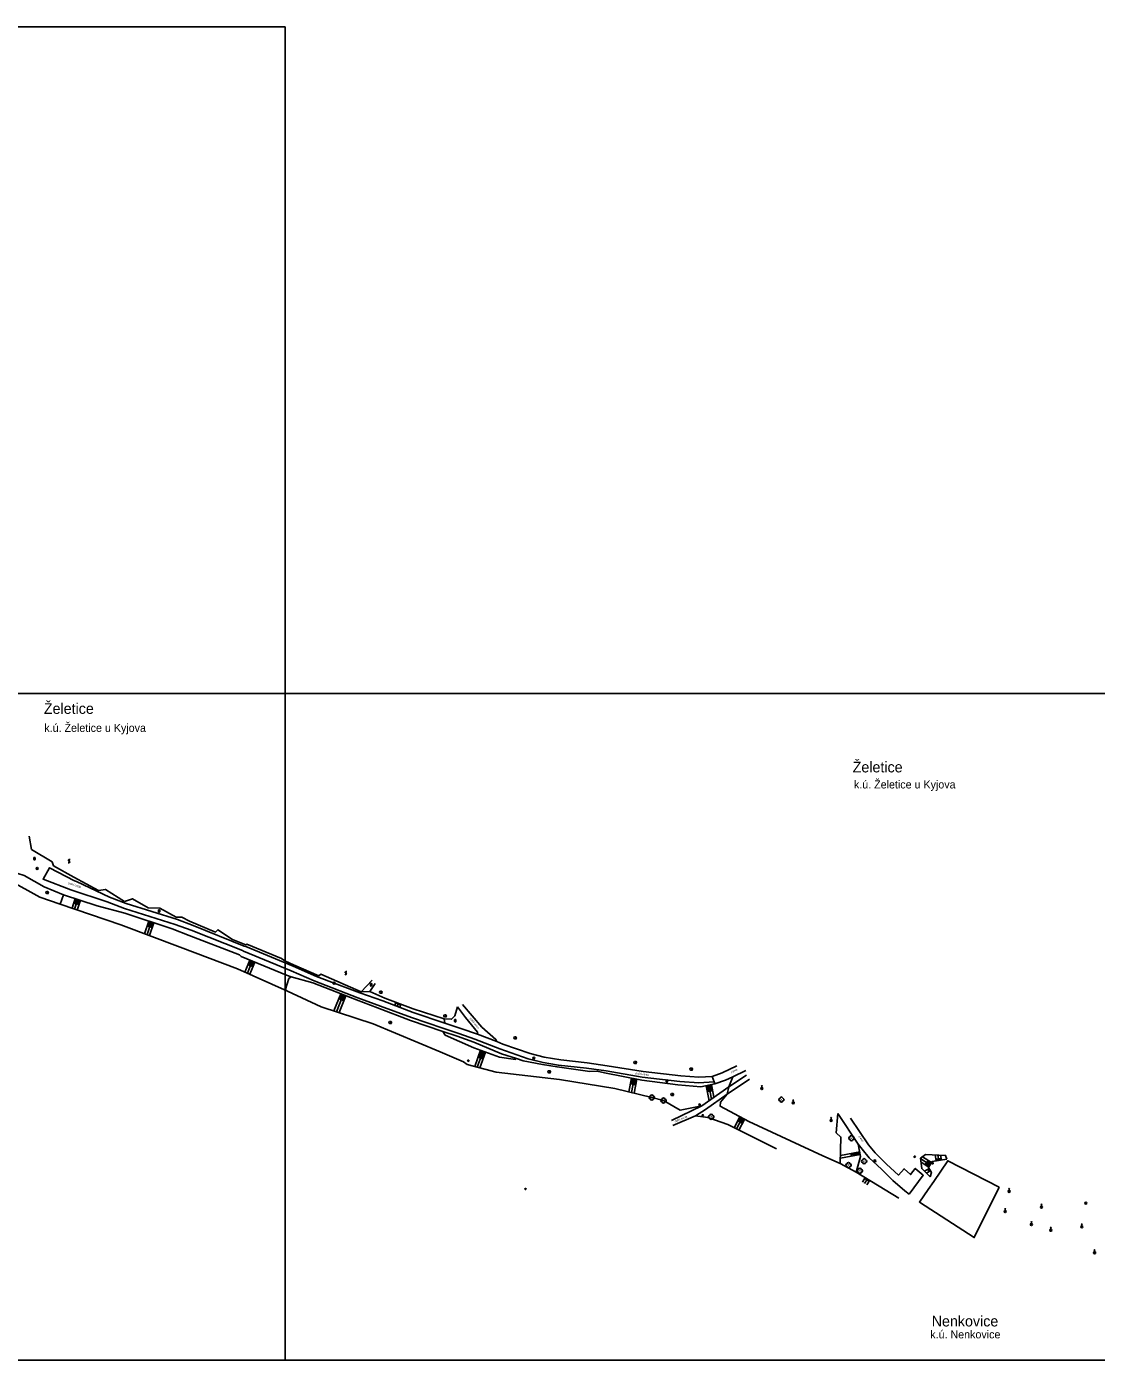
# Model space of a CAD drawing. Extents: x -582188 to -561562, y -1187250 to -1183500.
# Drawn here: x -571347 to -570946, y -1184500 to -1184000 of the extents above; entities that cross this region are included whole.
import ezdxf

# ---------------------------------------------------------------- set-up
doc = ezdxf.new("R2010")
doc.units = 0
for name, color, linetype in [('MAP_ZN_BP', 7, 'Continuous'), ('NÁZEV_K_Ú', 7, 'Continuous'), ('NÁZVY_SÍDEL_JEDNOTKY', 7, 'Continuous'), ('POMOC_POPIS', 7, 'Continuous'), ('ROZHRANÍ_PLOCH', 7, 'Continuous'), ('RÁMY_ML', 7, 'Continuous'), ('VÝŠKOPIS', 7, 'Continuous'), ('ZELEŇ', 7, 'Continuous'), ('ZN_BP', 7, 'Continuous'), ('ZN_DOPLŇKOVÉ', 7, 'Continuous'), ('ZN_KULTUR', 7, 'Continuous')]:
    doc.layers.add(name, color=color, linetype=linetype)

msp = doc.modelspace()

# ---------------------------------------------------------------- linework, layer by layer
at = {"layer": 'MAP_ZN_BP'}
for centre, radius in [((-571343.06, -1184315.59), 0.375), ((-571343.06, -1184315.59), 0.0005), ((-571231.72, -1184358.561), 0.375), ((-571231.72, -1184358.561), 0.0005), ((-571156.81, -1184386.731), 0.375), ((-571156.81, -1184386.731), 0.0005), ((-571028.93, -1184425.261), 0.375), ((-571028.93, -1184425.261), 0.0005), ((-570949.78, -1184441.12), 0.375), ((-570949.78, -1184441.12), 0.0005)]:
    msp.add_circle(centre, radius, dxfattribs=at)
at = {"layer": 'ROZHRANÍ_PLOCH'}
for points in [[(-571089.16, -1184395.62), (-571094.86, -1184395.95), (-571101.98, -1184395.41), (-571116.09, -1184393.81), (-571129.7, -1184391.51), (-571137.06, -1184390.51), (-571147.55, -1184389.37), (-571153.34, -1184388.33), (-571158.92, -1184387), (-571169.49, -1184383.21), (-571178.94, -1184379.58), (-571184.94, -1184377.41), (-571190.88, -1184375.45), (-571202.72, -1184371.53), (-571214.26, -1184367.24), (-571222.82, -1184364.08), (-571239.22, -1184357.73), (-571247.8, -1184353.97), (-571265.71, -1184346.54), (-571266.1, -1184346.29), (-571285.34, -1184338.73), (-571291.31, -1184336.61), (-571310.31, -1184330.62), (-571316.86, -1184328.14), (-571330.4, -1184323.55), (-571340.82, -1184319.56), (-571338.39, -1184315.32), (-571329.1, -1184320.28)], [(-571089.84, -1184393.57), (-571094.93, -1184393.8), (-571101.68, -1184393.3), (-571115.78, -1184391.71), (-571129.29, -1184389.55), (-571136.83, -1184388.51), (-571146.69, -1184387.3), (-571152.86, -1184386.34), (-571158.11, -1184385.02), (-571168.45, -1184381.46), (-571170.71, -1184380.45), (-571177.93, -1184377.76), (-571184.17, -1184375.65), (-571190.11, -1184373.58), (-571202.01, -1184369.63), (-571213.41, -1184365.22), (-571222.06, -1184362.26), (-571238.26, -1184356.04), (-571247.1, -1184352.22), (-571264.74, -1184344.9), (-571265.37, -1184344.68), (-571284.58, -1184336.94), (-571290.43, -1184334.78), (-571309.64, -1184328.69), (-571315.95, -1184326.36), (-571328.25, -1184320.45), (-571329.1, -1184320.28)], [(-571185.46, -1184367.46), (-571182.4, -1184371.5), (-571177.97, -1184376.96), (-571177.93, -1184377.76)], [(-571170.71, -1184380.45), (-571171, -1184379.71), (-571176.28, -1184375.11), (-571183.59, -1184366.57)], [(-571077.33, -1184391.35), (-571082.12, -1184393.7), (-571084.93, -1184394.98), (-571088.87, -1184396.39), (-571089.16, -1184395.62), (-571089.84, -1184393.57), (-571086.16, -1184392.21), (-571080.68, -1184389.64)], [(-571077.06, -1184393.03), (-571083.6, -1184397.43), (-571093.73, -1184404.56), (-571105.1, -1184410.06)], [(-571075.95, -1184394.6), (-571084.33, -1184400.24), (-571092.44, -1184405.94), (-571096.14, -1184408.32), (-571104.62, -1184411.95)], [(-571016.05, -1184437.72), (-571017.64, -1184436.48), (-571022.2, -1184432.55), (-571026.4, -1184428.33), (-571031.01, -1184424.08), (-571033.6, -1184420.87), (-571035.08, -1184418.93), (-571042.73, -1184407.49)], [(-571016.05, -1184437.72), (-571010.71, -1184430.59), (-571013.71, -1184428.08), (-571015.48, -1184430.36), (-571017.92, -1184428.16), (-571020, -1184430.58), (-571024.48, -1184426.41), (-571028.78, -1184422.18), (-571031.3, -1184419.18), (-571037.99, -1184409.26)]]:
    msp.add_lwpolyline(points, dxfattribs=at)
at = {"layer": 'RÁMY_ML'}
for points in [[(-571250, -1184000), (-571562.5, -1184000), (-571875, -1184000), (-573437.5, -1184000)], [(-571250, -1184000), (-571250, -1184500)], [(-570625, -1184250), (-570937.5, -1184250), (-571875, -1184250), (-572187.5, -1184250), (-572500, -1184250), (-572812.5, -1184250), (-573750, -1184250), (-574062.5, -1184250), (-574375, -1184250)], [(-570312.5, -1184500), (-571250, -1184500), (-571562.5, -1184500)]]:
    msp.add_lwpolyline(points, dxfattribs=at)
at = {"layer": 'VÝŠKOPIS'}
for p, q in [((-571328.77, -1184326.9), (-571329.98, -1184330.54)), ((-571327.82, -1184327.21), (-571329.03, -1184330.86)), ((-571328.3, -1184327.06), (-571328.92, -1184328.93)), ((-571326.87, -1184327.53), (-571328.09, -1184331.18)), ((-571327.35, -1184327.37), (-571327.97, -1184329.25)), ((-571301.22, -1184335.38), (-571302.76, -1184340.05)), ((-571300.27, -1184335.7), (-571301.83, -1184340.4)), ((-571300.75, -1184335.54), (-571301.41, -1184337.54)), ((-571299.32, -1184336.01), (-571300.89, -1184340.75)), ((-571299.8, -1184335.85), (-571300.46, -1184337.85)), ((-571263.31, -1184349.95), (-571265.14, -1184354.46)), ((-571262.38, -1184350.32), (-571264.22, -1184354.87)), ((-571262.85, -1184350.14), (-571263.65, -1184352.13)), ((-571261.46, -1184350.7), (-571263.31, -1184355.28)), ((-571261.92, -1184350.51), (-571262.73, -1184352.51)), ((-571229.2, -1184362.57), (-571231.74, -1184369.02)), ((-571228.27, -1184362.94), (-571230.79, -1184369.33)), ((-571227.34, -1184363.31), (-571229.84, -1184369.65)), ((-571228.74, -1184362.76), (-571229.56, -1184364.85)), ((-571227.81, -1184363.12), (-571228.63, -1184365.22)), ((-571208.94, -1184366.95), (-571208.5, -1184365.75)), ((-571208.25, -1184366.53), (-571208.03, -1184365.93)), ((-571208.01, -1184367.31), (-571207.56, -1184366.1)), ((-571207.32, -1184366.88), (-571207.09, -1184366.28)), ((-571207.08, -1184367.67), (-571206.62, -1184366.45)), ((-571190.11, -1184373.58), (-571190.45, -1184372)), ((-571176.75, -1184383.78), (-571178.97, -1184389.84)), ((-571175.81, -1184384.12), (-571178, -1184390.1)), ((-571176.28, -1184383.95), (-571177.29, -1184386.69)), ((-571174.87, -1184384.47), (-571177.03, -1184390.35)), ((-571175.34, -1184384.29), (-571176.35, -1184387.04)), ((-571120.1, -1184394.21), (-571121.13, -1184399.39)), ((-571119.12, -1184394.4), (-571120.16, -1184399.63)), ((-571119.61, -1184394.31), (-571120.08, -1184396.65)), ((-571118.14, -1184394.6), (-571119.19, -1184399.86)), ((-571118.63, -1184394.5), (-571119.1, -1184396.85)), ((-571092.14, -1184397.03), (-571091.04, -1184402.67)), ((-571091.65, -1184396.93), (-571091.18, -1184399.36)), ((-571091.16, -1184396.84), (-571090.14, -1184402.03)), ((-571090.67, -1184396.74), (-571090.19, -1184399.17)), ((-571090.18, -1184396.65), (-571089.25, -1184401.4)), ((-571079.51, -1184408.73), (-571081.7, -1184412.79)), ((-571078.63, -1184409.2), (-571080.8, -1184413.23)), ((-571079.07, -1184408.97), (-571080.03, -1184410.75)), ((-571077.75, -1184409.68), (-571079.9, -1184413.68)), ((-571078.19, -1184409.44), (-571079.15, -1184411.23)), ((-571034.35, -1184422.81), (-571041.78, -1184424.2)), ((-571034.54, -1184421.82), (-571041.76, -1184423.18)), ((-571034.45, -1184422.31), (-571037.96, -1184422.97)), ((-571008.1, -1184426.69), (-571011.68, -1184424.51)), ((-571007.58, -1184425.83), (-571011.04, -1184423.72)), ((-571005.9, -1184425.23), (-571006.23, -1184423.01)), ((-571005.4, -1184425.15), (-571005.53, -1184424.34)), ((-571004.91, -1184425.08), (-571005.22, -1184423.05)), ((-571004.41, -1184425), (-571004.54, -1184424.19)), ((-571003.92, -1184424.93), (-571004.2, -1184423.08)), ((-571008.62, -1184427.54), (-571011.55, -1184425.76)), ((-571008.57, -1184428.05), (-571010.3, -1184429.12)), ((-571008.36, -1184427.11), (-571009.96, -1184426.14)), ((-571008.04, -1184428.9), (-571009.58, -1184429.85)), ((-571007.84, -1184426.26), (-571009.44, -1184425.29)), ((-571008.3, -1184428.47), (-571009.04, -1184428.93)), ((-571032.51, -1184431.46), (-571033.57, -1184433.19)), ((-571031.66, -1184431.98), (-571032.72, -1184433.71)), ((-571032.08, -1184431.72), (-571032.44, -1184432.3)), ((-571030.81, -1184432.5), (-571031.86, -1184434.23)), ((-571031.23, -1184432.24), (-571031.58, -1184432.82))]:
    msp.add_line(p, q, dxfattribs=at)
for points in [[(-571334.44, -1184329.04), (-571311.74, -1184336.69), (-571289.41, -1184345.04), (-571267.89, -1184353.23), (-571249.18, -1184361.59)], [(-571247.8, -1184356.17), (-571249.49, -1184355.54), (-571266.52, -1184348.65), (-571267.13, -1184347.98), (-571286.09, -1184340.77), (-571292.46, -1184338.28), (-571310.22, -1184332.41), (-571320.55, -1184329.63), (-571333.16, -1184325.44)], [(-571218.28, -1184361.74), (-571221.55, -1184361.89), (-571222.06, -1184362.26)], [(-571163.25, -1184386.8), (-571163.7, -1184387.24), (-571169.6, -1184386.4), (-571179.28, -1184382.85), (-571190, -1184378.06), (-571190.87, -1184376.76)], [(-571019.91, -1184439.19), (-571025.03, -1184436.04), (-571035.84, -1184429.42), (-571041.83, -1184426.24), (-571048.4, -1184423.39), (-571076.2, -1184410.51), (-571086.85, -1184404.77), (-571086.71, -1184403.16), (-571084.33, -1184400.24), (-571083.6, -1184397.43), (-571082.12, -1184393.7)], [(-571096.14, -1184408.32), (-571091.58, -1184408.95), (-571084.06, -1184411.62), (-571065.76, -1184420.68)], [(-571042.73, -1184407.49), (-571043.37, -1184414.65), (-571041.61, -1184416.3), (-571041.83, -1184426.24)], [(-571035.08, -1184418.93), (-571034.21, -1184423.57), (-571035.84, -1184429.42)], [(-571008.19, -1184431.24), (-571011.29, -1184428.13), (-571011.71, -1184424.23), (-571009.93, -1184422.88), (-571002.37, -1184423.15), (-571001.9, -1184424.62)], [(-571008.19, -1184431.24), (-571007.64, -1184429.54), (-571008.75, -1184427.75), (-571007.35, -1184425.45), (-571001.9, -1184424.62)]]:
    msp.add_lwpolyline(points, dxfattribs=at)
at = {"layer": 'ZELEŇ'}
for points in [[(-571217.36, -1184357.49), (-571221.55, -1184361.89), (-571236.7, -1184355.19), (-571237.42, -1184355.84), (-571246.95, -1184351.74), (-571250.15, -1184350.27), (-571251.37, -1184349.38), (-571264.47, -1184343.97), (-571264.84, -1184344.18), (-571269.85, -1184342.23), (-571275.29, -1184338.59), (-571276.14, -1184339.44), (-571285.9, -1184335.39), (-571288.85, -1184333.88), (-571290.95, -1184333.87), (-571297.06, -1184330.44), (-571301.49, -1184330.41), (-571307.33, -1184326.94), (-571310.31, -1184328.01), (-571317.46, -1184323.42), (-571320.01, -1184323.87), (-571329.36, -1184318.84), (-571336.92, -1184314.55), (-571337.44, -1184313.14), (-571345.14, -1184308.48), (-571346.08, -1184303.44)], [(-571333.16, -1184325.44), (-571340.43, -1184322.47), (-571347.92, -1184318.26), (-571350.33, -1184317.45), (-571353.51, -1184319.99), (-571342.05, -1184326.41), (-571334.44, -1184329.04), (-571333.16, -1184325.44)], [(-571088.87, -1184396.39), (-571094.13, -1184397.42), (-571102.74, -1184396.76), (-571116.32, -1184394.96), (-571130.23, -1184392.2), (-571132.98, -1184391.59), (-571135.78, -1184391.68), (-571148.09, -1184390.02), (-571153.55, -1184389.09), (-571160.78, -1184387.73), (-571163.25, -1184386.8), (-571168.85, -1184385.07), (-571179.31, -1184380.7), (-571185.51, -1184378.47), (-571190.87, -1184376.76), (-571203.1, -1184372.59), (-571215.4, -1184367.81), (-571223.34, -1184364.88), (-571239.61, -1184358.48), (-571247.8, -1184356.17), (-571248.73, -1184356.86), (-571249.9, -1184360.81), (-571249.18, -1184361.59), (-571236.55, -1184367.41), (-571217.09, -1184373.9), (-571191.86, -1184384.4), (-571183.11, -1184388.03)], [(-571185.46, -1184367.46), (-571186.44, -1184370.86), (-571187.63, -1184372.12), (-571190.45, -1184372), (-571201.98, -1184368.18), (-571212.67, -1184364.2), (-571218.28, -1184361.74), (-571216.3, -1184358.74)], [(-571093.73, -1184404.56), (-571101.91, -1184406.18), (-571108.14, -1184402.62), (-571112.53, -1184401.5), (-571126.45, -1184398.08), (-571147.13, -1184394.66), (-571170.88, -1184391.96), (-571181.82, -1184389.1), (-571183.11, -1184388.03)]]:
    msp.add_lwpolyline(points, dxfattribs=at)
for centre in [(-571112.53, -1184401.5), (-571108.14, -1184402.62), (-571063.95, -1184402.26), (-571090.24, -1184408.7), (-571037.67, -1184416.72), (-571038.74, -1184426.8), (-571034.48, -1184428.92), (-571032.92, -1184425.38)]:
    msp.add_circle(centre, 0.0005, dxfattribs=at)
for centre, start, end in [((-571113.03, -1184401.5), 89.99999, 269.99999), ((-571112.53, -1184401), 0, 179.99999), ((-571112.53, -1184402), 179.99999, 359.99999), ((-571112.03, -1184401.5), 270, 89.99999), ((-571108.64, -1184402.62), 89.99999, 269.99999), ((-571108.14, -1184402.12), 0, 179.99999), ((-571108.14, -1184403.12), 179.99999, 359.99999), ((-571107.64, -1184402.62), 270, 89.99999), ((-571064.45, -1184402.26), 89.99999, 269.99999), ((-571063.95, -1184401.76), 0, 179.99999), ((-571063.95, -1184402.76), 179.99999, 359.99999), ((-571063.45, -1184402.26), 270, 89.99999), ((-571090.74, -1184408.7), 89.99999, 269.99999), ((-571090.24, -1184408.2), 0, 179.99999), ((-571090.24, -1184409.2), 179.99999, 359.99999), ((-571089.74, -1184408.7), 270, 89.99999), ((-571038.17, -1184416.72), 89.99999, 269.99999), ((-571037.67, -1184416.22), 0, 179.99999), ((-571037.67, -1184417.22), 179.99999, 359.99999), ((-571037.17, -1184416.72), 270, 89.99999), ((-571033.42, -1184425.38), 89.99999, 269.99999), ((-571032.92, -1184424.88), 0, 179.99999), ((-571032.42, -1184425.38), 270, 89.99999), ((-571039.24, -1184426.8), 89.99999, 269.99999), ((-571038.74, -1184426.3), 0, 179.99999), ((-571038.74, -1184427.3), 179.99999, 359.99999), ((-571038.24, -1184426.8), 270, 89.99999), ((-571034.98, -1184428.92), 89.99999, 269.99999), ((-571034.48, -1184428.42), 0, 179.99999), ((-571034.48, -1184429.42), 179.99999, 359.99999), ((-571033.98, -1184428.92), 270, 89.99999), ((-571032.92, -1184425.88), 179.99999, 359.99999)]:
    msp.add_arc(centre, 0.5, start, end, dxfattribs=at)
at = {"layer": 'ZN_BP'}
for p, q in [((-571071.515, -1184398.364), (-571070.986, -1184397.836)), ((-571070.986, -1184398.368), (-571071.515, -1184397.836)), ((-571071.25, -1184397.725), (-571071.25, -1184396.975)), ((-571059.735, -1184403.744), (-571059.206, -1184403.216)), ((-571059.206, -1184403.748), (-571059.735, -1184403.216)), ((-571059.47, -1184403.105), (-571059.47, -1184402.355)), ((-571045.555, -1184410.324), (-571045.026, -1184409.796)), ((-571045.026, -1184410.328), (-571045.555, -1184409.796)), ((-571045.29, -1184409.685), (-571045.29, -1184408.935)), ((-570978.805, -1184436.914), (-570978.276, -1184436.386)), ((-570978.276, -1184436.918), (-570978.805, -1184436.386)), ((-570978.54, -1184436.275), (-570978.54, -1184435.525)), ((-570980.225, -1184444.504), (-570979.696, -1184443.976)), ((-570979.696, -1184444.508), (-570980.225, -1184443.976)), ((-570979.96, -1184443.865), (-570979.96, -1184443.115)), ((-570966.675, -1184442.824), (-570966.146, -1184442.296)), ((-570966.146, -1184442.828), (-570966.675, -1184442.296)), ((-570966.41, -1184442.185), (-570966.41, -1184441.435)), ((-570970.445, -1184449.344), (-570969.916, -1184448.816)), ((-570969.916, -1184449.348), (-570970.445, -1184448.816)), ((-570970.18, -1184448.705), (-570970.18, -1184447.955)), ((-570951.535, -1184450.224), (-570951.006, -1184449.696)), ((-570951.006, -1184450.228), (-570951.535, -1184449.696)), ((-570951.27, -1184449.585), (-570951.27, -1184448.835)), ((-570963.165, -1184451.514), (-570962.636, -1184450.986)), ((-570962.636, -1184451.518), (-570963.165, -1184450.986)), ((-570962.9, -1184450.875), (-570962.9, -1184450.125)), ((-570946.715, -1184459.904), (-570946.186, -1184459.376)), ((-570946.186, -1184459.908), (-570946.715, -1184459.376)), ((-570946.45, -1184459.265), (-570946.45, -1184458.515))]:
    msp.add_line(p, q, dxfattribs=at)
for points in [[(-571071.375, -1184397.225), (-571071.25, -1184396.975), (-571071.125, -1184397.225)], [(-571059.595, -1184402.605), (-571059.47, -1184402.355), (-571059.345, -1184402.605)], [(-571045.415, -1184409.185), (-571045.29, -1184408.935), (-571045.165, -1184409.185)], [(-570978.665, -1184435.775), (-570978.54, -1184435.525), (-570978.415, -1184435.775)], [(-570980.085, -1184443.365), (-570979.96, -1184443.115), (-570979.835, -1184443.365)], [(-570966.535, -1184441.685), (-570966.41, -1184441.435), (-570966.285, -1184441.685)], [(-570970.305, -1184448.205), (-570970.18, -1184447.955), (-570970.055, -1184448.205)], [(-570951.395, -1184449.085), (-570951.27, -1184448.835), (-570951.145, -1184449.085)], [(-570963.025, -1184450.375), (-570962.9, -1184450.125), (-570962.775, -1184450.375)], [(-570946.575, -1184458.765), (-570946.45, -1184458.515), (-570946.325, -1184458.765)]]:
    msp.add_lwpolyline(points, dxfattribs=at)
for centre, radius in [((-571181.35, -1184387.67), 0.25), ((-571181.35, -1184387.67), 0.0005), ((-571071.25, -1184398.1), 0.375), ((-571094.63, -1184404.1), 0.25), ((-571094.63, -1184404.1), 0.0005), ((-571059.47, -1184403.48), 0.375), ((-571093.41, -1184408.17), 0.25), ((-571093.41, -1184408.17), 0.0005), ((-571045.29, -1184410.06), 0.375), ((-571007.24, -1184426.1), 0.25), ((-571007.24, -1184426.1), 0.0005), ((-571159.91, -1184435.77), 0.25), ((-571159.91, -1184435.77), 0.0005), ((-570978.54, -1184436.65), 0.375), ((-570979.96, -1184444.24), 0.375), ((-570966.41, -1184442.56), 0.375), ((-570970.18, -1184449.08), 0.375), ((-570951.27, -1184449.96), 0.375), ((-570962.9, -1184451.25), 0.375), ((-570946.45, -1184459.64), 0.375)]:
    msp.add_circle(centre, radius, dxfattribs=at)
at = {"layer": 'ZN_DOPLŇKOVÉ'}
msp.add_line((-571006.75, -1184432.94), (-571008.88, -1184435.9), dxfattribs=at)
for points in [[(-570982.29, -1184435.13), (-571001.56, -1184425.19), (-571006.75, -1184432.94)], [(-571008.88, -1184435.9), (-571012.14, -1184440.68), (-570991.58, -1184454.01), (-570982.29, -1184435.13)]]:
    msp.add_lwpolyline(points, dxfattribs=at)
for radius in [0.25, 0.0005]:
    msp.add_circle((-571013.941, -1184423.66), radius, dxfattribs=at)
at = {"layer": 'ZN_KULTUR'}
for p, q in [((-571344.57, -1184311.9), (-571343.57, -1184311.9)), ((-571344.32, -1184312.15), (-571344.32, -1184311.65)), ((-571343.82, -1184312.15), (-571343.82, -1184311.65)), ((-571331.485, -1184313.487), (-571331.11, -1184313.437)), ((-571331.11, -1184313.487), (-571331.11, -1184312.237)), ((-571330.735, -1184312.237), (-571331.11, -1184312.287)), ((-571339.46, -1184324.985), (-571338.835, -1184324.985)), ((-571297.84, -1184331.55), (-571296.84, -1184331.55)), ((-571297.59, -1184331.8), (-571297.59, -1184331.3)), ((-571297.09, -1184331.8), (-571297.09, -1184331.3)), ((-571227.32, -1184355.437), (-571227.32, -1184354.187)), ((-571226.945, -1184354.187), (-571227.32, -1184354.237)), ((-571227.695, -1184355.437), (-571227.32, -1184355.387)), ((-571218.31, -1184359.19), (-571217.31, -1184359.19)), ((-571218.06, -1184359.44), (-571218.06, -1184358.94)), ((-571217.56, -1184359.44), (-571217.56, -1184358.94)), ((-571214.32, -1184362.315), (-571213.695, -1184362.315)), ((-571210.76, -1184373.705), (-571210.135, -1184373.705)), ((-571190.22, -1184371.245), (-571189.595, -1184371.245)), ((-571186.73, -1184372.7), (-571185.73, -1184372.7)), ((-571186.48, -1184372.95), (-571186.48, -1184372.45)), ((-571185.98, -1184372.95), (-571185.98, -1184372.45)), ((-571163.92, -1184379.495), (-571163.295, -1184379.495)), ((-571118.89, -1184388.685), (-571118.265, -1184388.685)), ((-571151.11, -1184392.165), (-571150.485, -1184392.165)), ((-571097.84, -1184391.155), (-571097.215, -1184391.155)), ((-571107.37, -1184395.34), (-571106.37, -1184395.34)), ((-571107.12, -1184395.59), (-571107.12, -1184395.09)), ((-571106.62, -1184395.59), (-571106.62, -1184395.09)), ((-571104.99, -1184400.695), (-571104.365, -1184400.695))]:
    msp.add_line(p, q, dxfattribs=at)
for centre in [(-571339.46, -1184324.61), (-571214.32, -1184361.94), (-571210.76, -1184373.33), (-571190.22, -1184370.87), (-571163.92, -1184379.12), (-571118.89, -1184388.31), (-571151.11, -1184391.79), (-571097.84, -1184390.78), (-571104.99, -1184400.32)]:
    msp.add_circle(centre, 0.375, dxfattribs=at)
for centre, radius, start, end in [((-571344.07, -1184311.65), 0.25, 0, 179.99999), ((-571344.07, -1184312.15), 0.25, 179.99999, 359.99999), ((-571331.055, -1184312.565), 0.278, 99.96503, 253.49773), ((-571331.165, -1184313.131), 0.306, 280.37026, 79.03333), ((-571339.21, -1184324.61), 0.375, 249.49437, 109.04743), ((-571297.34, -1184331.3), 0.25, 0, 179.99999), ((-571297.34, -1184331.8), 0.25, 179.99999, 359.99999), ((-571227.265, -1184354.515), 0.278, 99.96503, 253.49773), ((-571227.375, -1184355.081), 0.306, 280.37026, 79.03333), ((-571217.81, -1184358.94), 0.25, 0, 179.99999), ((-571217.81, -1184359.44), 0.25, 179.99999, 359.99999), ((-571214.07, -1184361.94), 0.375, 249.49437, 109.04743), ((-571210.51, -1184373.33), 0.375, 249.49437, 109.04743), ((-571189.97, -1184370.87), 0.375, 249.49437, 109.04743), ((-571186.23, -1184372.45), 0.25, 0, 179.99999), ((-571186.23, -1184372.95), 0.25, 179.99999, 359.99999), ((-571163.67, -1184379.12), 0.375, 249.49437, 109.04743), ((-571118.64, -1184388.31), 0.375, 249.49437, 109.04743), ((-571150.86, -1184391.79), 0.375, 249.49437, 109.04743), ((-571106.87, -1184395.09), 0.25, 0, 179.99999), ((-571097.59, -1184390.78), 0.375, 249.49437, 109.04743), ((-571106.87, -1184395.59), 0.25, 179.99999, 359.99999), ((-571104.74, -1184400.32), 0.375, 249.49437, 109.04743)]:
    msp.add_arc(centre, radius, start, end, dxfattribs=at)

# ---------------------------------------------------------------- texts
at = {"layer": 'NÁZEV_K_Ú'}
for s, p in [('k.ú. Želetice u Kyjova', (-571340.39, -1184264.39)), ('k.ú. Želetice u Kyjova', (-571036.73, -1184285.6)), ('k.ú. Nenkovice', (-571008.1, -1184491.77))]:
    msp.add_text(s, height=3, dxfattribs=at).set_placement(p)
at = {"layer": 'NÁZVY_SÍDEL_JEDNOTKY'}
for s, p in [('Želetice', (-571340.54, -1184257.64)), ('Želetice', (-571037.2, -1184279.58)), ('Nenkovice', (-571007.56, -1184487.3))]:
    msp.add_text(s, height=4, dxfattribs=at).set_placement(p)
at = {"layer": 'POMOC_POPIS'}
for s, rotation, p in [('polní cesta', 341.27357, (-571331.48, -1184321.36)), ('polní cesta', 309.05433, (-571180.9, -1184371.9)), ('polní cesta', 352.26263, (-571118.65, -1184392.68)), ('panel', 23.32345, (-571082.66, -1184392.3)), ('polní cesta', 23.17412, (-571103.78, -1184410.82)), ('panel', 304.30813, (-571035.04, -1184416.09))]:
    msp.add_text(s, height=0.75, rotation=rotation, dxfattribs=at).set_placement(p)

doc.saveas('drawing.dxf')
